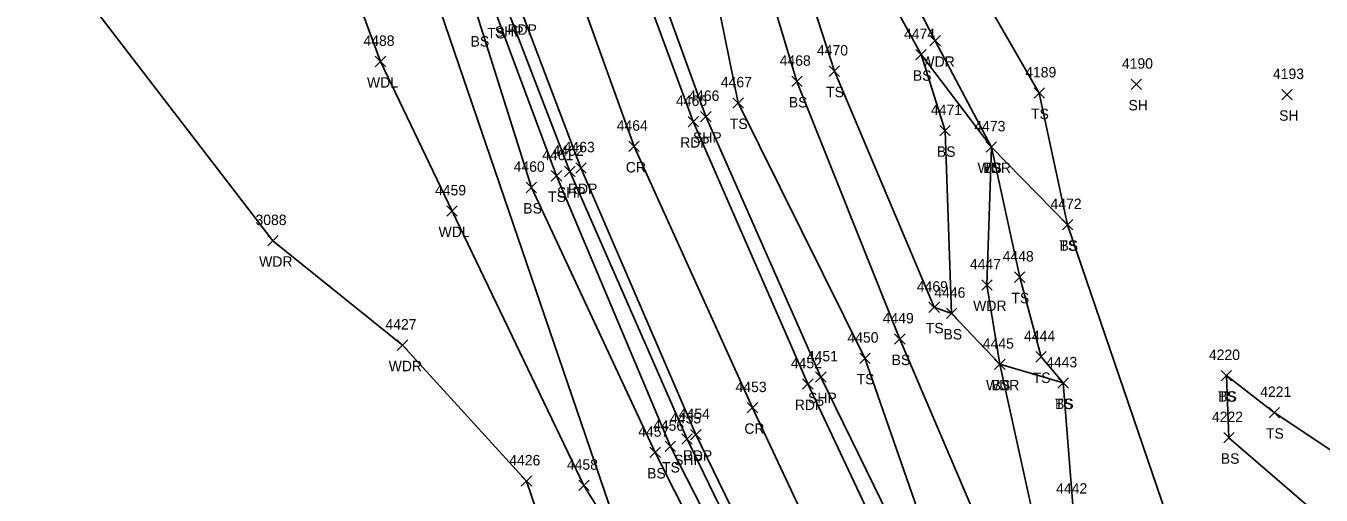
# Model space of a CAD drawing. Extents: x 1601151 to 1602912, y 499508 to 501770.
# Drawn here: x 1601639.1 to 1601887.2, y 499996 to 500086 of the extents above; entities that cross this region are included whole.
import ezdxf

# ---------------------------------------------------------------- set-up
doc = ezdxf.new("R2010")
doc.units = 0
for name, color, linetype in [('L_A', 7, 'Continuous'), ('L_I', 7, 'Continuous'), ('L_TIC', 7, 'Continuous'), ('LAWA', 7, 'Continuous'), ('LELB', 7, 'Continuous'), ('P_A', 7, 'Continuous'), ('P_I', 7, 'Continuous'), ('P_TIC', 7, 'Continuous'), ('PET', 7, 'Continuous'), ('PRC', 7, 'Continuous'), ('PSP', 7, 'Continuous'), ('UCO', 7, 'Continuous')]:
    doc.layers.add(name, color=color, linetype=linetype)

msp = doc.modelspace()

# ---------------------------------------------------------------- linework, layer by layer
at = {"layer": 'L_TIC'}
for points in [[(1601812.25, 500082.11), (1601814.25, 500084.11)], [(1601814.25, 500082.11), (1601812.25, 500084.11)], [(1601706.02, 500078.12), (1601708.02, 500080.12)], [(1601708.02, 500078.12), (1601706.02, 500080.12)], [(1601809.54, 500079.44), (1601811.54, 500081.44)], [(1601811.54, 500079.44), (1601809.54, 500081.44)], [(1601809.54, 500079.44), (1601811.54, 500081.44)], [(1601811.54, 500079.44), (1601809.54, 500081.44)], [(1601792.95, 500076.28), (1601794.95, 500078.28)], [(1601794.95, 500076.28), (1601792.95, 500078.28)], [(1601785.77, 500074.31), (1601787.77, 500076.31)], [(1601787.77, 500074.31), (1601785.77, 500076.31)], [(1601850.79, 500073.75), (1601852.79, 500075.75)], [(1601852.79, 500073.75), (1601850.79, 500075.75)], [(1601774.51, 500070.18), (1601776.51, 500072.18)], [(1601776.51, 500070.18), (1601774.51, 500072.18)], [(1601832.19, 500072.08), (1601834.19, 500074.08)], [(1601834.19, 500072.08), (1601832.19, 500074.08)], [(1601879.63, 500071.77), (1601881.63, 500073.77)], [(1601881.63, 500071.77), (1601879.63, 500073.77)], [(1601814.13, 500064.85), (1601816.13, 500066.85)], [(1601816.13, 500064.85), (1601814.13, 500066.85)], [(1601823.01, 500061.73), (1601825.01, 500063.73)], [(1601825.01, 500061.73), (1601823.01, 500063.73)], [(1601823.01, 500061.73), (1601825.01, 500063.73)], [(1601825.01, 500061.73), (1601823.01, 500063.73)], [(1601823.01, 500061.73), (1601825.01, 500063.73)], [(1601825.01, 500061.73), (1601823.01, 500063.73)], [(1601739.72, 500056.2), (1601741.72, 500058.2)], [(1601741.72, 500056.2), (1601739.72, 500058.2)], [(1601734.92, 500053.97), (1601736.92, 500055.97)], [(1601736.92, 500053.97), (1601734.92, 500055.97)], [(1601719.73, 500049.45), (1601721.73, 500051.45)], [(1601721.73, 500049.45), (1601719.73, 500051.45)], [(1601837.6, 500046.83), (1601839.6, 500048.83)], [(1601839.6, 500046.83), (1601837.6, 500048.83)], [(1601837.6, 500046.83), (1601839.6, 500048.83)], [(1601839.6, 500046.83), (1601837.6, 500048.83)], [(1601685.42, 500043.76), (1601687.42, 500045.76)], [(1601687.42, 500043.76), (1601685.42, 500045.76)], [(1601822.16, 500035.28), (1601824.16, 500037.28)], [(1601824.16, 500035.28), (1601822.16, 500037.28)], [(1601828.43, 500036.77), (1601830.43, 500038.77)], [(1601830.43, 500036.77), (1601828.43, 500038.77)], [(1601812.05, 500030.99), (1601814.05, 500032.99)], [(1601814.05, 500030.99), (1601812.05, 500032.99)], [(1601815.4, 500029.82), (1601817.4, 500031.82)], [(1601817.4, 500029.82), (1601815.4, 500031.82)], [(1601710.23, 500023.72), (1601712.23, 500025.72)], [(1601712.23, 500023.72), (1601710.23, 500025.72)], [(1601805.47, 500024.9), (1601807.47, 500026.9)], [(1601807.47, 500024.9), (1601805.47, 500026.9)], [(1601798.79, 500021.21), (1601800.79, 500023.21)], [(1601800.79, 500021.21), (1601798.79, 500023.21)], [(1601832.53, 500021.48), (1601834.53, 500023.48)], [(1601834.53, 500021.48), (1601832.53, 500023.48)], [(1601824.63, 500020.05), (1601826.63, 500022.05)], [(1601826.63, 500020.05), (1601824.63, 500022.05)], [(1601824.63, 500020.05), (1601826.63, 500022.05)], [(1601826.63, 500020.05), (1601824.63, 500022.05)], [(1601868.01, 500017.88), (1601870.01, 500019.88)], [(1601870.01, 500017.88), (1601868.01, 500019.88)], [(1601868.01, 500017.88), (1601870.01, 500019.88)], [(1601870.01, 500017.88), (1601868.01, 500019.88)], [(1601836.76, 500016.47), (1601838.76, 500018.47)], [(1601838.76, 500016.47), (1601836.76, 500018.47)], [(1601836.76, 500016.47), (1601838.76, 500018.47)], [(1601838.76, 500016.47), (1601836.76, 500018.47)], [(1601877.18, 500010.79), (1601879.18, 500012.79)], [(1601879.18, 500010.79), (1601877.18, 500012.79)], [(1601868.51, 500005.98), (1601870.51, 500007.98)], [(1601870.51, 500005.98), (1601868.51, 500007.98)], [(1601758.63, 500003.16), (1601760.63, 500005.16)], [(1601760.63, 500003.16), (1601758.63, 500005.16)], [(1601761.54, 500004.3), (1601763.54, 500006.3)], [(1601763.54, 500004.3), (1601761.54, 500006.3)], [(1601733.99, 499997.67), (1601735.99, 499999.67)], [(1601735.99, 499997.67), (1601733.99, 499999.67)], [(1601744.98, 499996.83), (1601746.98, 499998.83)], [(1601746.98, 499996.83), (1601744.98, 499998.83)]]:
    msp.add_lwpolyline(points, dxfattribs=at)
at = {"layer": 'LAWA'}
for points in [[(1602022.55, 499813.65), (1601986.23, 499821.98), (1601948.47, 499842.78), (1601932.99, 499850.05), (1601908.71, 499876.98), (1601895.51, 499891.37), (1601872.45, 499928.68), (1601860.91, 499944.04), (1601845.01, 499958.8), (1601833.19, 499986.79), (1601825.63, 500021.05), (1601823.16, 500036.28), (1601824.01, 500062.73), (1601813.25, 500083.11), (1601795.9, 500116.91), (1601787.61, 500146.09), (1601789.07, 500162.65), (1601789.86, 500175.08), (1601780.36, 500177.88), (1601766.38, 500200.64), (1601744.62, 500238.97)], [(1601686.42, 500044.76), (1601647.16, 500095.94), (1601645.77, 500132.47), (1601691.58, 500118.74)], [(1601800.97, 499910.85), (1601789.31, 499928.29), (1601745.98, 499997.83), (1601720.73, 500050.45), (1601707.02, 500079.12), (1601696.06, 500108.93)], [(1601711.23, 500024.72), (1601686.42, 500044.76)], [(1601795.59, 499904.88), (1601774.51, 499904.9), (1601765.47, 499909.24), (1601751.16, 499931.75), (1601765.12, 499947.71), (1601747.4, 499962.08), (1601734.99, 499998.67), (1601711.23, 500024.72)]]:
    msp.add_lwpolyline(points, dxfattribs=at)
at = {"layer": 'LELB'}
for points in [[(1601817.31, 499872.7), (1601822.26, 499874.94), (1601824.19, 499882.19), (1601820.64, 499891.83), (1601797.18, 499933.64), (1601778.06, 499967.49), (1601759.63, 500004.16), (1601735.92, 500054.97), (1601725.84, 500087), (1601715.25, 500119.3), (1601698.06, 500177.62), (1601684.73, 500227.08), (1601672.09, 500269.9), (1601659.22, 500313.1), (1601655.82, 500330.46)], [(1601820.64, 499891.83), (1601799.69, 499935.32), (1601781.01, 499969.12), (1601762.54, 500005.3), (1601740.72, 500057.2), (1601729.05, 500088.56), (1601717.64, 500121.66), (1601699.62, 500177.82), (1601686.02, 500227.23), (1601673.93, 500270.73), (1601661.95, 500313.91), (1601655.82, 500330.46)], [(1601931.2, 499782.14), (1601903.71, 499827.94), (1601870.02, 499876.47), (1601851.57, 499910.98), (1601830.01, 499949.1), (1601812.84, 499984.56), (1601799.79, 500022.21), (1601775.51, 500071.18), (1601768.77, 500104.65), (1601752.69, 500132.35), (1601745.59, 500147.03), (1601736.89, 500188.62), (1601718.63, 500236.24), (1601706.47, 500280.22)], [(1601760.67, 500243.76), (1601792.66, 500172.01), (1601798.78, 500160.53), (1601810.28, 500122.09), (1601819.47, 500096.84), (1601833.19, 500073.08)], [(1601813.05, 500031.99), (1601793.95, 500077.28), (1601782.98, 500111.24), (1601751.34, 500194.46), (1601732.94, 500239.75)], [(1601837.76, 500017.47), (1601825.63, 500021.05), (1601816.4, 500030.82), (1601815.13, 500065.85), (1601810.54, 500080.44), (1601791.57, 500115.27), (1601782.56, 500143.38), (1601776.74, 500166.52), (1601761.8, 500197.32), (1601744.62, 500238.97)], [(1601903.71, 499827.94), (1601874.05, 499878.65), (1601857.01, 499914.55), (1601837.68, 499952.04), (1601821.99, 499989.47), (1601806.47, 500025.9), (1601786.77, 500075.31), (1601776.8, 500108.45), (1601758.74, 500135.39), (1601750.45, 500149.06), (1601745.01, 500191.77), (1601725.55, 500237.57)], [(1601838.6, 500047.83), (1601824.01, 500062.73), (1601810.54, 500080.44)], [(1601833.19, 500073.08), (1601838.6, 500047.83)], [(1601839.67, 499993.25), (1601837.76, 500017.47), (1601833.53, 500022.48), (1601829.43, 500037.77), (1601824.01, 500062.73)], [(1601871.03, 499952.67), (1601838.6, 500047.83)], [(1601816.4, 500030.82), (1601813.05, 500031.99)], [(1601869.01, 500018.88), (1601869.51, 500006.98), (1601901.98, 499978.89), (1601950.31, 499963.52), (1601960.93, 499964.27)], [(1601869.01, 500018.88), (1601878.18, 500011.79), (1601912.56, 499988.85), (1601951, 499971.65), (1601959.04, 499993.64)]]:
    msp.add_lwpolyline(points, dxfattribs=at)
at = {"layer": 'P_TIC'}
for points in [[(1601768.33, 500067.57), (1601770.33, 500069.57)], [(1601770.33, 500067.57), (1601768.33, 500069.57)], [(1601765.92, 500066.61), (1601767.92, 500068.61)], [(1601767.92, 500066.61), (1601765.92, 500068.61)], [(1601754.57, 500061.85), (1601756.57, 500063.85)], [(1601756.57, 500061.85), (1601754.57, 500063.85)], [(1601744.41, 500057.72), (1601746.41, 500059.72)], [(1601746.41, 500057.72), (1601744.41, 500059.72)], [(1601742.28, 500057.03), (1601744.28, 500059.03)], [(1601744.28, 500057.03), (1601742.28, 500059.03)], [(1601787.87, 500016.29), (1601789.87, 500018.29)], [(1601789.87, 500016.29), (1601787.87, 500018.29)], [(1601790.36, 500017.61), (1601792.36, 500019.61)], [(1601792.36, 500017.61), (1601790.36, 500019.61)], [(1601777.27, 500011.72), (1601779.27, 500013.72)], [(1601779.27, 500011.72), (1601777.27, 500013.72)], [(1601764.73, 500005.71), (1601766.73, 500007.71)], [(1601766.73, 500005.71), (1601764.73, 500007.71)], [(1601766.41, 500006.57), (1601768.41, 500008.57)], [(1601768.41, 500006.57), (1601766.41, 500008.57)]]:
    msp.add_lwpolyline(points, dxfattribs=at)
at = {"layer": 'PET'}
for points in [[(1601995.67, 499683.24), (1601967.44, 499723.89), (1601951.2, 499747.81), (1601928.38, 499780.82), (1601898.7, 499825.12), (1601866.23, 499874.79), (1601846.19, 499907.84), (1601823.76, 499946.63), (1601805.55, 499981.9), (1601788.87, 500017.29), (1601766.92, 500067.61), (1601755.39, 500098.81), (1601743.92, 500129.72), (1601726.45, 500185.71), (1601711.93, 500234.21), (1601699.42, 500278.31), (1601688.33, 500319.61), (1601682.56, 500342.8), (1601675.53, 500367.54), (1601665.76, 500404.47), (1601656.17, 500441.2), (1601643.95, 500489.36), (1601630.25, 500541.68)], [(1601976.03, 499671.31), (1601949.07, 499710.22), (1601932.5, 499734.59), (1601906.16, 499773.6), (1601879.17, 499813.54), (1601846.78, 499862.77), (1601825.9, 499896.89), (1601802.83, 499936.77), (1601785.08, 499971.15), (1601767.41, 500007.57), (1601745.41, 500058.72), (1601733.84, 500089.25), (1601721.8, 500122.71), (1601703.99, 500178.99), (1601689.71, 500228.27), (1601677.58, 500272.25), (1601666.12, 500315.05), (1601653.43, 500363.86), (1601644.59, 500397.8), (1601635.03, 500435.31), (1601622.92, 500483.99), (1601609.64, 500536.46)]]:
    msp.add_lwpolyline(points, dxfattribs=at)
at = {"layer": 'PRC'}
msp.add_lwpolyline([(1601985.39, 499677.47), (1601958.56, 499716.67), (1601942.32, 499739.6), (1601916.26, 499778.51), (1601888.68, 499819.15), (1601856.54, 499869.05), (1601836.01, 499902.11), (1601813.37, 499942.52), (1601794.98, 499977.03), (1601778.27, 500012.72), (1601755.57, 500062.85), (1601744.49, 500093.78), (1601732.77, 500126.07), (1601715.37, 500182.36), (1601700.57, 500231.28), (1601688.37, 500275.57), (1601676.78, 500317.03), (1601664.23, 500365.85), (1601655.24, 500401.01), (1601645.63, 500438.14), (1601632.99, 500486.74), (1601619.53, 500538.88)], dxfattribs=at)
at = {"layer": 'PSP'}
for points in [[(1601997, 499684.27), (1601969.14, 499725.42), (1601931.2, 499782.14), (1601900.18, 499826.03), (1601867.9, 499875.39), (1601847.37, 499908.8), (1601829.13, 499940.29), (1601829, 499944.33), (1601827.07, 499947.93), (1601808.69, 499983.01), (1601791.36, 500018.61), (1601769.33, 500068.57), (1601758.08, 500099.65), (1601747.15, 500130.33), (1601730.42, 500186.97), (1601714.57, 500235.16), (1601709.05, 500248.69), (1601701, 500279.76), (1601693.52, 500306.69)], [(1601974.74, 499670.12), (1601948.09, 499709.66), (1601931.04, 499733.86), (1601904.81, 499772.45), (1601877.68, 499812.76), (1601851.66, 499852.31), (1601848.35, 499852.94), (1601832.41, 499878.84), (1601831.77, 499883.88), (1601824.29, 499896.03), (1601801.22, 499936.03), (1601783.34, 499970.29), (1601765.73, 500006.71), (1601743.28, 500058.03), (1601731.38, 500088.89), (1601719.94, 500122.25), (1601702, 500178.56), (1601687.75, 500227.8), (1601675.97, 500271.58)]]:
    msp.add_lwpolyline(points, dxfattribs=at)
at = {"layer": 'UCO'}
msp.add_lwpolyline([(1601870.49, 499699.14), (1601777.6, 499915.52), (1601705.51, 500127.03), (1601650.89, 500325.1)], dxfattribs=at)

# ---------------------------------------------------------------- texts
at = {"layer": 'L_A'}
for s, p in [('TS', (1601727.46, 500083.56)), ('BS', (1601724.28, 500082)), ('WDR', (1601810.61, 500078.11)), ('BS', (1601808.98, 500075.44)), ('BS', (1601808.98, 500075.44)), ('WDL', (1601704.43, 500074.12)), ('BS', (1601785.22, 500070.31)), ('TS', (1601792.36, 500072.28)), ('TS', (1601831.6, 500068.08)), ('SH', (1601850.27, 500069.75)), ('SH', (1601879.12, 500067.77)), ('TS', (1601773.92, 500066.18)), ('BS', (1601813.57, 500060.85)), ('WDR', (1601821.37, 500057.73)), ('TS', (1601822.42, 500057.73)), ('BS', (1601822.45, 500057.73)), ('TS', (1601739.13, 500052.2)), ('BS', (1601734.36, 500049.97)), ('WDL', (1601718.14, 500045.45)), ('TS', (1601837.01, 500042.83)), ('BS', (1601837.04, 500042.83)), ('WDR', (1601683.78, 500039.76)), ('TS', (1601827.84, 500032.77)), ('WDR', (1601820.52, 500031.28)), ('TS', (1601811.46, 500026.99)), ('BS', (1601814.84, 500025.82)), ('BS', (1601804.91, 500020.9)), ('WDR', (1601708.59, 500019.72)), ('TS', (1601798.2, 500017.21)), ('WDR', (1601822.99, 500016.05)), ('BS', (1601824.07, 500016.05)), ('TS', (1601831.94, 500017.48)), ('TS', (1601867.42, 500013.88)), ('BS', (1601867.45, 500013.88)), ('TS', (1601836.17, 500012.47)), ('BS', (1601836.2, 500012.47)), ('TS', (1601876.59, 500006.79)), ('BS', (1601867.95, 500001.98)), ('BS', (1601758.07, 499999.16)), ('TS', (1601760.95, 500000.3))]:
    msp.add_text(s, height=2, dxfattribs=at).set_placement(p)
at = {"layer": 'L_I'}
for s, p in [('4474', (1601807.28, 500083.44)), ('4474', (1601807.28, 500083.44)), ('4488', (1601703.76, 500082.12)), ('4470', (1601790.61, 500080.28)), ('4468', (1601783.47, 500078.31)), ('4190', (1601849.01, 500077.75)), ('4189', (1601830.49, 500076.08)), ('4193', (1601877.93, 500075.77)), ('4467', (1601772.2, 500074.18)), ('4471', (1601812.44, 500068.85)), ('4473', (1601820.75, 500065.73)), ('4473', (1601820.75, 500065.73)), ('4473', (1601820.75, 500065.73)), ('4461', (1601737.98, 500060.2)), ('4460', (1601732.52, 500057.97)), ('4459', (1601717.46, 500053.45)), ('4472', (1601835.34, 500050.83)), ('4472', (1601835.34, 500050.83)), ('3088', (1601683.08, 500047.76)), ('4448', (1601826.17, 500040.77)), ('4447', (1601819.9, 500039.28)), ('4469', (1601809.73, 500034.99)), ('4446', (1601813.09, 500033.82)), ('4427', (1601707.97, 500027.72)), ('4449', (1601803.2, 500028.9)), ('4444', (1601830.27, 500025.48)), ('4450', (1601796.44, 500025.21)), ('4445', (1601822.37, 500024.05)), ('4445', (1601822.37, 500024.05)), ('4443', (1601834.5, 500020.47)), ('4443', (1601834.5, 500020.47)), ('4220', (1601865.67, 500021.88)), ('4220', (1601865.67, 500021.88)), ('4221', (1601875.49, 500014.79)), ('4456', (1601759.22, 500008.3)), ('4222', (1601866.25, 500009.98)), ('4457', (1601756.37, 500007.16)), ('4426', (1601731.68, 500001.67)), ('4458', (1601742.72, 500000.83)), ('4442', (1601836.41, 499996.25))]:
    msp.add_text(s, height=2, dxfattribs=at).set_placement(p)
at = {"layer": 'P_A'}
for s, p in [('SHP', (1601728.92, 500083.89)), ('RDP', (1601731.33, 500084.25)), ('RDP', (1601764.41, 500062.61)), ('SHP', (1601766.86, 500063.57)), ('CR', (1601754, 500057.85)), ('SHP', (1601740.82, 500053.03)), ('RDP', (1601742.9, 500053.72)), ('SHP', (1601788.9, 500013.61)), ('RDP', (1601786.36, 500012.29)), ('CR', (1601776.7, 500007.72)), ('SHP', (1601763.26, 500001.71)), ('RDP', (1601764.9, 500002.57))]:
    msp.add_text(s, height=2, dxfattribs=at).set_placement(p)
at = {"layer": 'P_I'}
for s, p in [('4465', (1601763.62, 500070.61)), ('4466', (1601765.97, 500071.57)), ('4464', (1601752.26, 500065.85)), ('4462', (1601739.98, 500061.03)), ('4463', (1601742.1, 500061.72)), ('4452', (1601785.61, 500020.29)), ('4451', (1601788.67, 500021.61)), ('4453', (1601775.01, 500015.72)), ('4454', (1601764.15, 500010.57)), ('4455', (1601762.47, 500009.71))]:
    msp.add_text(s, height=2, dxfattribs=at).set_placement(p)

doc.saveas('drawing.dxf')
